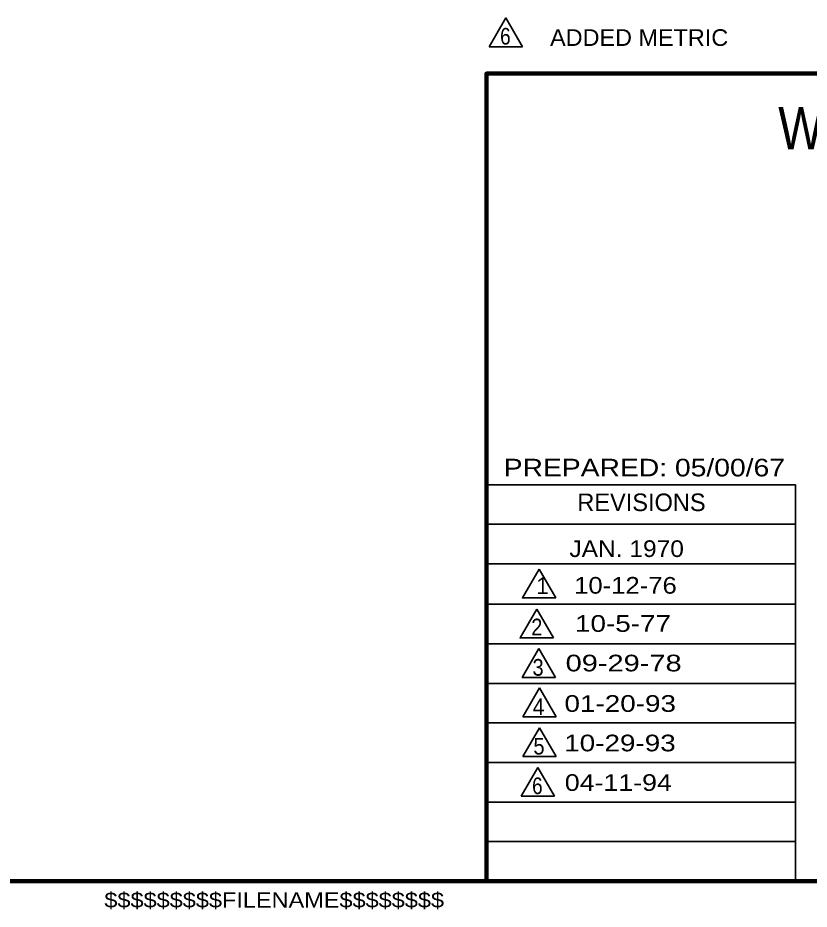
# Model space of a CAD drawing. Extents: x 442 to 1297, y -1132 to -588.
# Drawn here: x 1005.3 to 1119.2, y -1124.2 to -995.8 of the extents above; entities that cross this region are included whole.
import ezdxf
from ezdxf.enums import TextEntityAlignment as Align

# ---------------------------------------------------------------- set-up
doc = ezdxf.new("R2010")
doc.units = 0
doc.header["$LTSCALE"] = 0.96
doc.layers.add('1', color=7, linetype='Continuous', lineweight=35)

msp = doc.modelspace()

# ---------------------------------------------------------------- linework, layer by layer
at = {"layer": '1'}
for p, q in [((1075.5385, -995.8305), (1073.1385, -999.9874)), ((1075.5385, -995.8305), (1077.9385, -999.9874)), ((1073.1385, -999.9874), (1077.9385, -999.9874)), ((1117.2447, -1068.7679), (1072.7447, -1068.7679)), ((1117.2447, -1074.4679), (1072.7447, -1074.4679)), ((1080.3341, -1075.2177), (1082.7341, -1079.3746)), ((1117.2447, -1080.2679), (1072.7447, -1080.2679)), ((1080.009, -1080.9644), (1082.409, -1085.1213)), ((1117.2447, -1085.9679), (1072.7447, -1085.9679)), ((1080.3196, -1086.6481), (1082.7196, -1090.805)), ((1117.2447, -1091.6679), (1072.7447, -1091.6679)), ((1080.3946, -1092.3207), (1077.9946, -1096.4776)), ((1080.3946, -1092.3207), (1082.7946, -1096.4776)), ((1117.2447, -1097.3679), (1072.7447, -1097.3679)), ((1077.9946, -1096.4776), (1082.7946, -1096.4776)), ((1080.3897, -1098.0661), (1077.9897, -1102.223)), ((1080.3897, -1098.0661), (1082.7897, -1102.223)), ((1077.9897, -1102.223), (1082.7897, -1102.223)), ((1117.2447, -1103.0679), (1072.7447, -1103.0679)), ((1080.1458, -1103.7668), (1077.7458, -1107.9237)), ((1080.1458, -1103.7668), (1082.5458, -1107.9237)), ((1117.2447, -1108.7679), (1072.7447, -1108.7679)), ((1077.7458, -1107.9237), (1082.5458, -1107.9237)), ((1117.2447, -1114.4679), (1072.7447, -1114.4679))]:
    msp.add_line(p, q, dxfattribs=at)
at = {"layer": '1', "lineweight": 158}
msp.add_line((1290.7447, -1120.1679), (499.1447, -1120.1679), dxfattribs=at)
msp.add_lwpolyline([(1072.7447, -1120.1679), (1072.7447, -1003.8679), (1290.7447, -1003.8679)], dxfattribs=at)
at = {"layer": '1'}
for points in [[(1117.2447, -1120.1679), (1117.2447, -1063.0679), (1072.7447, -1063.0679)], [(1080.3341, -1075.2177), (1077.9341, -1079.3746), (1082.7341, -1079.3746)], [(1080.009, -1080.9644), (1077.609, -1085.1213), (1082.409, -1085.1213)], [(1080.3196, -1086.6481), (1077.9196, -1090.805), (1082.7196, -1090.805)]]:
    msp.add_lwpolyline(points, dxfattribs=at)

# ---------------------------------------------------------------- texts
for s, height, width, p in [('6', 2.4, 0.85, (1075.4866, -999.6835)), ('WEST VIRGINIA DIVISION OF HIGHWAYS', 6.089, 0.85, (1182.6447, -1014.7679)), ('JAN. 1970', 2.4, 1.1, (1092.949, -1073.4748)), ('2', 2.4, 0.9, (1080.0091, -1084.756)), ('3', 2.4, 0.9, (1080.1933, -1090.5661)), ('01-20-93', 2.4, 1.25, (1092.0245, -1095.7733)), ('4', 2.4, 0.95, (1080.2683, -1096.2387)), ('5', 2.4, 0.9, (1080.3284, -1101.9191)), ('10-29-93', 2.4, 1.25, (1091.9835, -1101.46)), ('04-11-94', 2.4, 1.2, (1091.7493, -1107.1607)), ('6', 2.4, 0.85, (1080.0939, -1107.6198))]:
    msp.add_text(s, height=height, dxfattribs=dict(at, width=width)).set_placement(p, align=Align.CENTER)
for s, height, width, p in [('ADDED METRIC', 2.4, 1.05, (1081.9229, -999.8728)), ('PREPARED: 05/00/67', 2.537, 1.2, (1075.2447, -1061.8679)), ('10-12-76', 2.4, 1.15, (1085.3911, -1078.7556)), ('10-5-77', 2.4, 1.25, (1085.5084, -1084.2497)), ('09-29-78', 2.4, 1.3, (1084.1626, -1089.946)), ('$$$$$$$$$FILENAME$$$$$$$$', 2.2, 1.15, (1017.7447, -1123.9679))]:
    msp.add_text(s, height=height, dxfattribs=dict(at, width=width)).set_placement(p)
msp.add_text('REVISIONS', height=2.537, dxfattribs=at).set_placement((1085.8447, -1066.8679))
msp.add_text('1', height=2.4, dxfattribs=at).set_placement((1080.8246, -1078.8197), align=Align.CENTER)

doc.saveas('drawing.dxf')
